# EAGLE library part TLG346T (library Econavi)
LED DISPLAY 1-character 7 segment, decimal point right
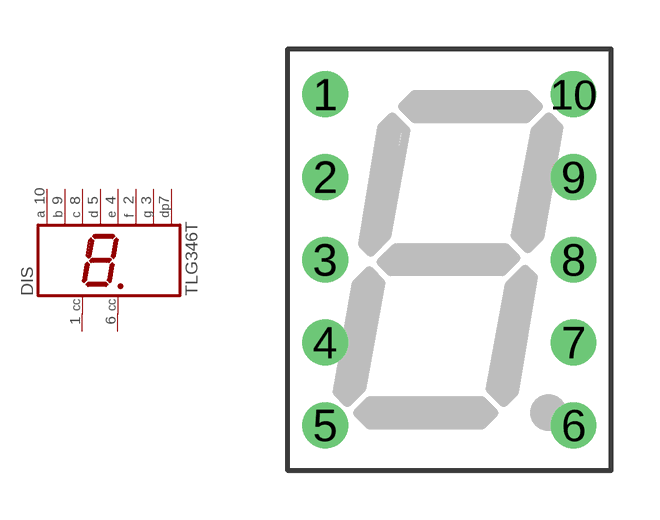
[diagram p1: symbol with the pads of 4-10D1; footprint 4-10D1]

Designator prefix DIS

## TLG346T  [4-10D1]
1  CA  pas
2  F  pas
3  G  pas
4  E  pas
5  D  pas
6  CA  pas
7  DP  pas
8  C  pas
9  B  pas
10  A  pas

## Footprint 4-10D1 (pad centres in mm)
LED DISPLAY 10-mm 1 character 7 segment, decimal point right
drill 0.9 round: 1 -3.81,5.08; 2 -3.81,2.54; 3 -3.81,0; 4 -3.81,-2.54; 5 -3.81,-5.08; 6 3.81,-5.08; 7 3.81,-2.54; 8 3.81,0; 9 3.81,2.54; 10 3.81,5.08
